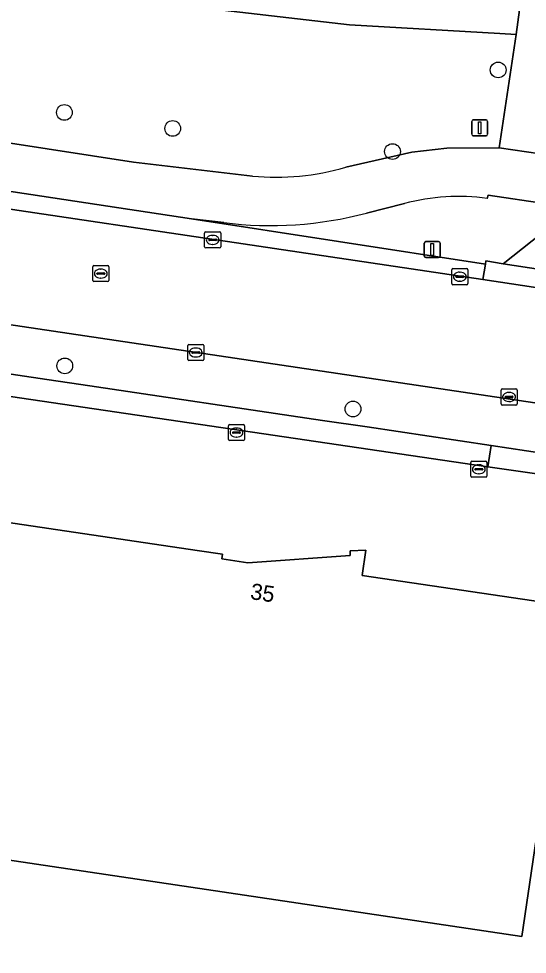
# Model space of a CAD drawing. Extents: x 163683 to 164494, y 382709 to 383872.
# Drawn here: x 164050.8 to 164082.5, y 382871.2 to 382929.4 of the extents above; entities that cross this region are included whole.
import ezdxf

# ---------------------------------------------------------------- set-up
doc = ezdxf.new("R2010")
doc.units = 0
for name, color, linetype in [('IMGEO_Berm_groen', 7, 'Continuous'), ('IMGEO_Boom', 7, 'Continuous'), ('IMGEO_Erf', 7, 'Continuous'), ('IMGEO_Fietspad_gesloten', 7, 'Continuous'), ('IMGEO_Groenvoorziening', 7, 'Continuous'), ('IMGEO_Kolk', 7, 'Continuous'), ('IMGEO_Lichtmast', 7, 'Continuous'), ('IMGEO_Pand', 7, 'Continuous'), ('IMGEO_Pand_nummerreeks', 7, 'Continuous'), ('IMGEO_Parkeervlak_open', 7, 'Continuous'), ('IMGEO_Rijbaan_lokaal_gesloten', 7, 'Continuous'), ('IMGEO_Rijbaan_lokaal_open', 7, 'Continuous'), ('IMGEO_Rioolput', 7, 'Continuous'), ('IMGEO_Verkeersbordpaal', 7, 'Continuous'), ('IMGEO_Voetpad_open', 7, 'Continuous')]:
    doc.layers.add(name, color=color, linetype=linetype)

msp = doc.modelspace()

# ---------------------------------------------------------------- linework, layer by layer
at = {"layer": 'IMGEO_Berm_groen'}
for points in [[(164083.489, 382916.871), (164083.648, 382917.908), (164080.015, 382918.445), (164079.969, 382918.239)], [(164074.822, 382917.914), (164072.46, 382917.324)], [(164063.573, 382916.731), (164061.579, 382916.967), (164079.851, 382914.143), (164079.881, 382914.352), (164080.954, 382914.16), (164083.365, 382916.067), (164083.489, 382916.871)]]:
    msp.add_lwpolyline(points, dxfattribs=at)
for centre, radius, start, end in [((164078.212, 382905.142), 13.214, 82.36027, 104.86586), ((164066.497, 382939.799), 23.253, 262.77587, 284.85912)]:
    msp.add_arc(centre, radius, start, end, dxfattribs=at)
at = {"layer": 'IMGEO_Boom'}
for centre in [(164080.645, 382926.223), (164053.665, 382923.58), (164060.402, 382922.586), (164074.07, 382921.15), (164053.691, 382907.822), (164071.613, 382905.143)]:
    msp.add_circle(centre, 0.489, dxfattribs=at)
at = {"layer": 'IMGEO_Erf'}
msp.add_lwpolyline([(164089.551, 382900.168), (164080.011, 382901.545), (164079.147, 382901.667), (164042.413, 382907.072), (164041.688, 382907.195), (164041.242, 382904.989), (164032.692, 382758.111), (164034.793, 382757.798), (164034.852, 382758.197), (164064.704, 382753.814), (164065.062, 382753.76), (164065.054, 382753.692), (164076.595, 382751.948), (164089.763, 382750)], dxfattribs=at)
msp.add_lwpolyline([(164045.234, 382877.827), (164046.187, 382883.846), (164046.041, 382883.87), (164048.336, 382898.347), (164061.914, 382896.34), (164063.498, 382896.105), (164063.459, 382895.814), (164065.07, 382895.583), (164071.442, 382896.029), (164071.431, 382896.326), (164072.411, 382896.362), (164072.195, 382894.782), (164085.244, 382892.851), (164085.183, 382892.441), (164085.07, 382892.457), (164082.112, 382872.347)], close=True, dxfattribs=at)
at = {"layer": 'IMGEO_Fietspad_gesloten'}
for points in [[(164065.362, 382919.619), (164057.956, 382920.485), (164050.038, 382921.718)], [(164088.61, 382920.207), (164084.114, 382920.888), (164080.709, 382921.39), (164077.448, 382921.353), (164075.274, 382921.115), (164071.17, 382920.18)], [(164047.717, 382919.05), (164061.579, 382916.967), (164063.573, 382916.731)], [(164079.969, 382918.239), (164080.015, 382918.445), (164083.648, 382917.908), (164088.11, 382917.218), (164091.819, 382916.666), (164091.798, 382916.497), (164093.404, 382916.027), (164098.222, 382913.466), (164101.705, 382911.946), (164104.433, 382911.123), (164109.452, 382909.801), (164122.324, 382907.915), (164124.915, 382908.091), (164127.365, 382908.358), (164132.887, 382909.267), (164136.538, 382909.996), (164140.34, 382909.47), (164145.688, 382908.677), (164167.355, 382905.668), (164170.356, 382905.251), (164178.004, 382904.232), (164188.016, 382903.301)], [(164072.46, 382917.324), (164074.822, 382917.914)]]:
    msp.add_lwpolyline(points, dxfattribs=at)
for centre, radius, start, end in [((164066.812, 382934.955), 15.404, 264.59943, 286.43484), ((164078.212, 382905.142), 13.214, 82.36027, 104.86586), ((164066.497, 382939.799), 23.253, 262.77587, 284.85912)]:
    msp.add_arc(centre, radius, start, end, dxfattribs=at)
at = {"layer": 'IMGEO_Groenvoorziening'}
for points in [[(164071.17, 382920.18), (164075.274, 382921.115), (164077.448, 382921.353), (164080.709, 382921.39), (164081.754, 382928.429), (164080.74, 382928.493), (164071.398, 382929.032), (164050.201, 382931.494), (164036.256, 382933.735), (164034.772, 382933.986), (164033.962, 382928.278), (164038.227, 382926.732), (164040.344, 382925.695), (164045.501, 382922.94)], [(164050.038, 382921.718), (164057.956, 382920.485), (164065.362, 382919.619)]]:
    msp.add_lwpolyline(points, dxfattribs=at)
msp.add_arc((164066.812, 382934.955), 15.404, 264.59943, 286.43484, dxfattribs=at)
at = {"layer": 'IMGEO_Kolk'}
for p, q in [((164062.387, 382915.232), (164062.387, 382916.084)), ((164062.462, 382916.158), (164063.314, 382916.158)), ((164063.388, 382916.084), (164063.388, 382915.232)), ((164062.646, 382915.652), (164062.646, 382915.664)), ((164063.084, 382915.615), (164062.686, 382915.615)), ((164062.689, 382915.701), (164063.087, 382915.701)), ((164062.875, 382915.938), (164062.9, 382915.938)), ((164063.13, 382915.664), (164063.13, 382915.652)), ((164063.314, 382915.158), (164062.462, 382915.158)), ((164062.898, 382915.378), (164062.873, 382915.378)), ((164077.759, 382912.943), (164077.759, 382913.795)), ((164077.834, 382913.869), (164078.686, 382913.869)), ((164078.76, 382913.795), (164078.76, 382912.943)), ((164078.018, 382913.363), (164078.018, 382913.375)), ((164078.456, 382913.326), (164078.058, 382913.326)), ((164078.061, 382913.412), (164078.459, 382913.412)), ((164078.247, 382913.649), (164078.272, 382913.649)), ((164078.502, 382913.375), (164078.502, 382913.363)), ((164078.686, 382912.869), (164077.834, 382912.869)), ((164078.27, 382913.089), (164078.245, 382913.089)), ((164061.409, 382909.154), (164062.261, 382909.154)), ((164061.334, 382908.228), (164061.334, 382909.08)), ((164061.593, 382908.648), (164061.593, 382908.66)), ((164062.031, 382908.611), (164061.633, 382908.611)), ((164061.636, 382908.697), (164062.034, 382908.697)), ((164061.822, 382908.934), (164061.847, 382908.934)), ((164062.077, 382908.66), (164062.077, 382908.648)), ((164062.335, 382909.08), (164062.335, 382908.228)), ((164062.261, 382908.154), (164061.409, 382908.154)), ((164061.845, 382908.374), (164061.82, 382908.374)), ((164080.822, 382905.461), (164080.822, 382906.313)), ((164080.897, 382906.387), (164081.749, 382906.387)), ((164081.823, 382906.313), (164081.823, 382905.461)), ((164081.081, 382905.881), (164081.081, 382905.893)), ((164081.519, 382905.844), (164081.121, 382905.844)), ((164081.124, 382905.93), (164081.522, 382905.93)), ((164081.31, 382906.167), (164081.335, 382906.167)), ((164081.565, 382905.893), (164081.565, 382905.881)), ((164081.749, 382905.387), (164080.897, 382905.387)), ((164081.333, 382905.607), (164081.308, 382905.607)), ((164063.866, 382903.251), (164063.866, 382904.103)), ((164063.941, 382904.177), (164064.793, 382904.177)), ((164064.354, 382903.957), (164064.379, 382903.957)), ((164064.867, 382904.103), (164064.867, 382903.251)), ((164064.125, 382903.671), (164064.125, 382903.683)), ((164064.563, 382903.634), (164064.165, 382903.634)), ((164064.168, 382903.72), (164064.566, 382903.72)), ((164064.377, 382903.397), (164064.352, 382903.397)), ((164064.609, 382903.683), (164064.609, 382903.671)), ((164064.793, 382903.177), (164063.941, 382903.177)), ((164078.941, 382900.966), (164078.941, 382901.818)), ((164079.016, 382901.892), (164079.868, 382901.892)), ((164079.429, 382901.672), (164079.454, 382901.672)), ((164079.942, 382901.818), (164079.942, 382900.966)), ((164079.2, 382901.386), (164079.2, 382901.398)), ((164079.638, 382901.349), (164079.24, 382901.349)), ((164079.243, 382901.435), (164079.641, 382901.435)), ((164079.452, 382901.112), (164079.427, 382901.112)), ((164079.684, 382901.398), (164079.684, 382901.386)), ((164079.868, 382900.892), (164079.016, 382900.892))]:
    msp.add_line(p, q, dxfattribs=at)
for points in [[(164062.387, 382915.232), (164062.387, 382916.084)], [(164062.462, 382916.158), (164063.314, 382916.158)], [(164063.388, 382916.084), (164063.388, 382915.232)], [(164063.314, 382915.158), (164062.462, 382915.158)], [(164077.759, 382912.943), (164077.759, 382913.795)], [(164077.834, 382913.869), (164078.686, 382913.869)], [(164078.76, 382913.795), (164078.76, 382912.943)], [(164078.686, 382912.869), (164077.834, 382912.869)], [(164061.409, 382909.154), (164062.261, 382909.154)], [(164061.334, 382908.228), (164061.334, 382909.08)], [(164062.335, 382909.08), (164062.335, 382908.228)], [(164062.261, 382908.154), (164061.409, 382908.154)], [(164080.822, 382905.461), (164080.822, 382906.313)], [(164080.897, 382906.387), (164081.749, 382906.387)], [(164081.823, 382906.313), (164081.823, 382905.461)], [(164081.749, 382905.387), (164080.897, 382905.387)], [(164063.866, 382903.251), (164063.866, 382904.103)], [(164063.941, 382904.177), (164064.793, 382904.177)], [(164064.867, 382904.103), (164064.867, 382903.251)], [(164064.793, 382903.177), (164063.941, 382903.177)], [(164078.941, 382900.966), (164078.941, 382901.818)], [(164079.016, 382901.892), (164079.868, 382901.892)], [(164079.942, 382901.818), (164079.942, 382900.966)], [(164079.868, 382900.892), (164079.016, 382900.892)]]:
    msp.add_lwpolyline(points, dxfattribs=at)
for centre, radius, start, end in [((164062.464, 382916.082), 0.0765, 91.55205, 178.44795), ((164062.464, 382916.082), 0.0765, 91.55205, 178.44795), ((164063.312, 382916.082), 0.0765, 1.55205, 88.44795), ((164063.312, 382916.082), 0.0765, 1.55205, 88.44795), ((164062.686, 382915.661), 0.0403, 85.87752, 175.75265), ((164062.683, 382915.651), 0.0366, 178.93798, 274.71019), ((164063.087, 382915.658), 0.043, 264.86636, 352.45326), ((164063.091, 382915.663), 0.0386, 1.73085, 96.63898), ((164062.464, 382915.234), 0.0765, 181.55205, 268.44795), ((164062.464, 382915.234), 0.0765, 181.55205, 268.44795), ((164063.312, 382915.234), 0.0765, 271.55205, 358.44795), ((164063.312, 382915.234), 0.0765, 271.55205, 358.44795), ((164077.836, 382913.793), 0.0765, 91.55205, 178.44795), ((164077.836, 382913.793), 0.0765, 91.55205, 178.44795), ((164078.684, 382913.793), 0.0765, 1.55205, 88.44795), ((164078.684, 382913.793), 0.0765, 1.55205, 88.44795), ((164078.058, 382913.372), 0.0403, 85.87752, 175.75265), ((164078.055, 382913.362), 0.0366, 178.93798, 274.71019), ((164078.459, 382913.369), 0.043, 264.86636, 352.45326), ((164078.463, 382913.374), 0.0386, 1.73085, 96.63898), ((164077.836, 382912.945), 0.0765, 181.55205, 268.44795), ((164077.836, 382912.945), 0.0765, 181.55205, 268.44795), ((164078.684, 382912.945), 0.0765, 271.55205, 358.44795), ((164078.684, 382912.945), 0.0765, 271.55205, 358.44795), ((164061.411, 382909.078), 0.0765, 91.55205, 178.44795), ((164061.411, 382909.078), 0.0765, 91.55205, 178.44795), ((164062.259, 382909.078), 0.0765, 1.55205, 88.44795), ((164062.259, 382909.078), 0.0765, 1.55205, 88.44795), ((164061.633, 382908.657), 0.0403, 85.87752, 175.75265), ((164061.63, 382908.647), 0.0366, 178.93798, 274.71019), ((164062.034, 382908.654), 0.043, 264.86636, 352.45326), ((164062.038, 382908.659), 0.0386, 1.73085, 96.63898), ((164061.411, 382908.23), 0.0765, 181.55205, 268.44795), ((164061.411, 382908.23), 0.0765, 181.55205, 268.44795), ((164062.259, 382908.23), 0.0765, 271.55205, 358.44795), ((164062.259, 382908.23), 0.0765, 271.55205, 358.44795), ((164080.899, 382906.311), 0.0765, 91.55205, 178.44795), ((164080.899, 382906.311), 0.0765, 91.55205, 178.44795), ((164081.747, 382906.311), 0.0765, 1.55205, 88.44795), ((164081.747, 382906.311), 0.0765, 1.55205, 88.44795), ((164081.121, 382905.89), 0.0403, 85.87752, 175.75265), ((164081.118, 382905.88), 0.0366, 178.93798, 274.71019), ((164081.522, 382905.887), 0.043, 264.86636, 352.45326), ((164081.526, 382905.892), 0.0386, 1.73085, 96.63898), ((164080.899, 382905.463), 0.0765, 181.55205, 268.44795), ((164080.899, 382905.463), 0.0765, 181.55205, 268.44795), ((164081.747, 382905.463), 0.0765, 271.55205, 358.44795), ((164081.747, 382905.463), 0.0765, 271.55205, 358.44795), ((164063.943, 382904.101), 0.0765, 91.55205, 178.44795), ((164063.943, 382904.101), 0.0765, 91.55205, 178.44795), ((164064.791, 382904.101), 0.0765, 1.55205, 88.44795), ((164064.791, 382904.101), 0.0765, 1.55205, 88.44795), ((164064.165, 382903.68), 0.0403, 85.87752, 175.75265), ((164064.162, 382903.67), 0.0366, 178.93798, 274.71019), ((164064.566, 382903.677), 0.043, 264.86636, 352.45326), ((164064.57, 382903.682), 0.0386, 1.73085, 96.63898), ((164063.943, 382903.253), 0.0765, 181.55205, 268.44795), ((164063.943, 382903.253), 0.0765, 181.55205, 268.44795), ((164064.791, 382903.253), 0.0765, 271.55205, 358.44795), ((164064.791, 382903.253), 0.0765, 271.55205, 358.44795), ((164079.018, 382901.816), 0.0765, 91.55205, 178.44795), ((164079.018, 382901.816), 0.0765, 91.55205, 178.44795), ((164079.866, 382901.816), 0.0765, 1.55205, 88.44795), ((164079.866, 382901.816), 0.0765, 1.55205, 88.44795), ((164079.018, 382900.968), 0.0765, 181.55205, 268.44795), ((164079.018, 382900.968), 0.0765, 181.55205, 268.44795), ((164079.24, 382901.395), 0.0403, 85.87752, 175.75265), ((164079.237, 382901.385), 0.0366, 178.93798, 274.71019), ((164079.641, 382901.392), 0.043, 264.86636, 352.45326), ((164079.645, 382901.397), 0.0386, 1.73085, 96.63898), ((164079.866, 382900.968), 0.0765, 271.55205, 358.44795), ((164079.866, 382900.968), 0.0765, 271.55205, 358.44795)]:
    msp.add_arc(centre, radius, start, end, dxfattribs=at)
for centre, major_axis, ratio, start_param, end_param in [((164062.874, 382915.658), (-0.387, 0.002), 0.722429, 4.712389, 7.853982), ((164062.899, 382915.658), (-0.39, 0.002), 0.717154, 1.570796, 4.712389), ((164078.246, 382913.369), (-0.387, 0.002), 0.722429, 4.712389, 7.853982), ((164078.271, 382913.369), (-0.39, 0.002), 0.717154, 1.570796, 4.712389), ((164061.821, 382908.654), (-0.387, 0.002), 0.722429, 4.712389, 7.853982), ((164061.846, 382908.654), (-0.39, 0.002), 0.717154, 1.570796, 4.712389), ((164081.309, 382905.887), (-0.387, 0.002), 0.722429, 4.712389, 7.853982), ((164081.334, 382905.887), (-0.39, 0.002), 0.717154, 1.570796, 4.712389), ((164064.353, 382903.677), (-0.387, 0.002), 0.722429, 4.712389, 7.853982), ((164064.378, 382903.677), (-0.39, 0.002), 0.717154, 1.570796, 4.712389), ((164079.428, 382901.392), (-0.387, 0.002), 0.722429, 4.712389, 7.853982), ((164079.453, 382901.392), (-0.39, 0.002), 0.717154, 1.570796, 4.712389)]:
    msp.add_ellipse(centre, major_axis=major_axis, ratio=ratio, start_param=start_param, end_param=end_param, dxfattribs=at)
at = {"layer": 'IMGEO_Lichtmast'}
for p, q in [((164076.146, 382915.553), (164076.936, 382915.553)), ((164076.936, 382915.553), (164076.146, 382915.553)), ((164076.046, 382914.653), (164076.046, 382915.453)), ((164076.046, 382915.453), (164076.046, 382914.653)), ((164077.036, 382915.453), (164077.036, 382914.653)), ((164077.036, 382914.653), (164077.036, 382915.453)), ((164076.936, 382914.553), (164076.146, 382914.553)), ((164076.146, 382914.553), (164076.936, 382914.553))]:
    msp.add_line(p, q, dxfattribs=at)
msp.add_lwpolyline([(164076.466, 382915.428), (164076.616, 382915.428), (164076.616, 382914.678), (164076.466, 382914.678), (164076.466, 382915.428)], dxfattribs=at)
for centre, start, end in [((164076.146, 382915.453), 90, 180), ((164076.146, 382915.453), 90, 180), ((164076.936, 382915.453), 0, 90), ((164076.936, 382915.453), 360, 90), ((164076.146, 382914.653), 180, 270), ((164076.146, 382914.653), 180, 270), ((164076.936, 382914.653), 270, 0), ((164076.936, 382914.653), 270, 0)]:
    msp.add_arc(centre, 0.1, start, end, dxfattribs=at)
at = {"layer": 'IMGEO_Pand'}
msp.add_lwpolyline([(164085.07, 382892.457), (164085.183, 382892.441), (164085.244, 382892.851), (164072.195, 382894.782), (164072.411, 382896.362), (164071.431, 382896.326), (164071.442, 382896.029), (164065.07, 382895.583), (164063.459, 382895.814), (164063.498, 382896.105), (164061.914, 382896.34), (164048.336, 382898.347), (164046.041, 382883.87), (164046.187, 382883.846), (164045.234, 382877.827), (164082.112, 382872.347)], close=True, dxfattribs=at)
at = {"layer": 'IMGEO_Parkeervlak_open'}
for points in [[(164166.332, 382893.113), (164033.326, 382912.894), (164021.113, 382914.698), (163965.93, 382922.852)], [(163975.455, 382918.386), (163993.603, 382915.695), (163995.696, 382915.393), (164011.29, 382913.202), (164013.239, 382912.818), (164014.541, 382912.605), (164025.865, 382910.928), (164031.6, 382910.081), (164032.786, 382909.904), (164033.609, 382909.781), (164042.707, 382908.456), (164052.577, 382906.985), (164054.697, 382906.667), (164069.708, 382904.418), (164072.487, 382904.039), (164080.21, 382902.866), (164086.798, 382901.866)]]:
    msp.add_lwpolyline(points, dxfattribs=at)
at = {"layer": 'IMGEO_Rijbaan_lokaal_gesloten'}
msp.add_lwpolyline([(163919.071, 382929.775), (163929.575, 382928.223), (163934.445, 382927.503), (163949.269, 382925.313), (163960.027, 382923.724), (163965.93, 382922.852), (164021.113, 382914.698), (164033.326, 382912.894), (164166.332, 382893.113), (164171.815, 382892.288), (164171.848, 382892.493), (164173.872, 382892.164), (164174.911, 382898.979), (164170.414, 382899.665), (164165.758, 382900.346), (164148.504, 382902.921), (164136.237, 382904.741), (164091.335, 382911.423), (164079.7, 382913.184), (164033.425, 382920.068), (164021.948, 382921.76), (164021.301, 382921.855), (163975.435, 382928.591), (163963.827, 382930.3)], dxfattribs=at)
at = {"layer": 'IMGEO_Rijbaan_lokaal_open'}
msp.add_lwpolyline([(164088.11, 382917.218), (164083.648, 382917.908), (164083.489, 382916.871), (164083.365, 382916.067), (164080.954, 382914.16), (164089.553, 382912.871), (164087.808, 382915.203)], close=True, dxfattribs=at)
at = {"layer": 'IMGEO_Rioolput'}
for p, q in [((164055.429, 382913.135), (164055.429, 382913.987)), ((164055.504, 382914.061), (164056.356, 382914.061)), ((164055.917, 382913.841), (164055.942, 382913.841)), ((164056.43, 382913.987), (164056.43, 382913.135)), ((164055.688, 382913.555), (164055.688, 382913.567)), ((164056.126, 382913.518), (164055.728, 382913.518)), ((164055.731, 382913.604), (164056.129, 382913.604)), ((164055.94, 382913.281), (164055.915, 382913.281)), ((164056.172, 382913.567), (164056.172, 382913.555)), ((164056.356, 382913.061), (164055.504, 382913.061))]:
    msp.add_line(p, q, dxfattribs=at)
for points in [[(164055.429, 382913.135), (164055.429, 382913.987)], [(164055.504, 382914.061), (164056.356, 382914.061)], [(164056.43, 382913.987), (164056.43, 382913.135)], [(164056.356, 382913.061), (164055.504, 382913.061)]]:
    msp.add_lwpolyline(points, dxfattribs=at)
for centre, radius, start, end in [((164055.506, 382913.985), 0.0765, 91.55205, 178.44795), ((164055.506, 382913.985), 0.0765, 91.55205, 178.44795), ((164056.354, 382913.985), 0.0765, 1.55205, 88.44795), ((164056.354, 382913.985), 0.0765, 1.55205, 88.44795), ((164055.728, 382913.564), 0.0403, 85.87752, 175.75265), ((164055.725, 382913.554), 0.0366, 178.93798, 274.71019), ((164056.129, 382913.561), 0.043, 264.86636, 352.45326), ((164056.133, 382913.566), 0.0386, 1.73085, 96.63898), ((164055.506, 382913.137), 0.0765, 181.55205, 268.44795), ((164055.506, 382913.137), 0.0765, 181.55205, 268.44795), ((164056.354, 382913.137), 0.0765, 271.55205, 358.44795), ((164056.354, 382913.137), 0.0765, 271.55205, 358.44795)]:
    msp.add_arc(centre, radius, start, end, dxfattribs=at)
for centre, major_axis, ratio, start_param, end_param in [((164055.916, 382913.561), (-0.387, 0.002), 0.722429, 4.712389, 7.853982), ((164055.941, 382913.561), (-0.39, 0.002), 0.717154, 1.570796, 4.712389)]:
    msp.add_ellipse(centre, major_axis=major_axis, ratio=ratio, start_param=start_param, end_param=end_param, dxfattribs=at)
at = {"layer": 'IMGEO_Verkeersbordpaal'}
for p, q in [((164079.098, 382923.124), (164079.888, 382923.124)), ((164079.888, 382923.124), (164079.098, 382923.124)), ((164078.998, 382922.224), (164078.998, 382923.024)), ((164078.998, 382923.024), (164078.998, 382922.224)), ((164079.988, 382923.024), (164079.988, 382922.224)), ((164079.988, 382922.224), (164079.988, 382923.024)), ((164079.888, 382922.124), (164079.098, 382922.124)), ((164079.098, 382922.124), (164079.888, 382922.124))]:
    msp.add_line(p, q, dxfattribs=at)
msp.add_lwpolyline([(164079.418, 382922.999), (164079.568, 382922.999), (164079.568, 382922.249), (164079.418, 382922.249), (164079.418, 382922.999)], dxfattribs=at)
for centre, start, end in [((164079.098, 382923.024), 90, 180), ((164079.098, 382923.024), 90, 180), ((164079.888, 382923.024), 0, 90), ((164079.888, 382923.024), 360, 90), ((164079.098, 382922.224), 180, 270), ((164079.098, 382922.224), 180, 270), ((164079.888, 382922.224), 270, 0), ((164079.888, 382922.224), 270, 0)]:
    msp.add_arc(centre, 0.1, start, end, dxfattribs=at)
at = {"layer": 'IMGEO_Voetpad_open'}
msp.add_lwpolyline([(164100.39, 383035.674), (164098.124, 383035.989), (164097.915, 383034.601), (164096.804, 383027.184), (164097.675, 383027.054), (164097.357, 383025.464), (164096.163, 383017.209), (164095.296, 383011.222), (164094.015, 383011.414), (164093.777, 383009.815), (164092.315, 383000), (164088.422, 382973.858), (164087.983, 382970.912), (164082.663, 382935.187), (164082.071, 382930.744), (164081.754, 382928.429), (164080.709, 382921.39), (164084.114, 382920.888), (164084.307, 382922.351), (164084.375, 382922.567)], dxfattribs=at)
for points in [[(164080.74, 382928.493), (164081.754, 382928.429), (164082.071, 382930.744), (164081.178, 382930.801), (164068.596, 382931.761), (164051.831, 382933.731), (164039.288, 382935.529), (164037.165, 382935.861), (164035.122, 382936.251), (164034.772, 382933.986), (164036.256, 382933.735), (164050.201, 382931.494), (164071.398, 382929.032)], [(164061.579, 382916.967), (164047.717, 382919.05), (164033.517, 382921.06), (164033.425, 382920.068), (164079.7, 382913.184), (164079.851, 382914.143)], [(164091.335, 382911.423), (164091.493, 382912.402), (164091.518, 382912.593), (164089.553, 382912.871), (164080.954, 382914.16), (164079.881, 382914.352), (164079.851, 382914.143), (164079.7, 382913.184)], [(164054.697, 382906.667), (164052.577, 382906.985), (164042.707, 382908.456), (164042.413, 382907.072), (164079.147, 382901.667), (164080.011, 382901.545), (164080.21, 382902.866), (164072.487, 382904.039), (164069.708, 382904.418)], [(164089.694, 382901.426), (164086.798, 382901.866), (164080.21, 382902.866), (164080.011, 382901.545), (164089.551, 382900.168), (164089.574, 382900.373)]]:
    msp.add_lwpolyline(points, close=True, dxfattribs=at)

# ---------------------------------------------------------------- texts
at = {"layer": 'IMGEO_Pand_nummerreeks'}
msp.add_text('35', height=1, rotation=351.56033, dxfattribs=at).set_placement((164065.187, 382893.327))

doc.saveas('drawing.dxf')
